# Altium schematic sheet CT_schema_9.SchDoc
size 274 x 160 mm
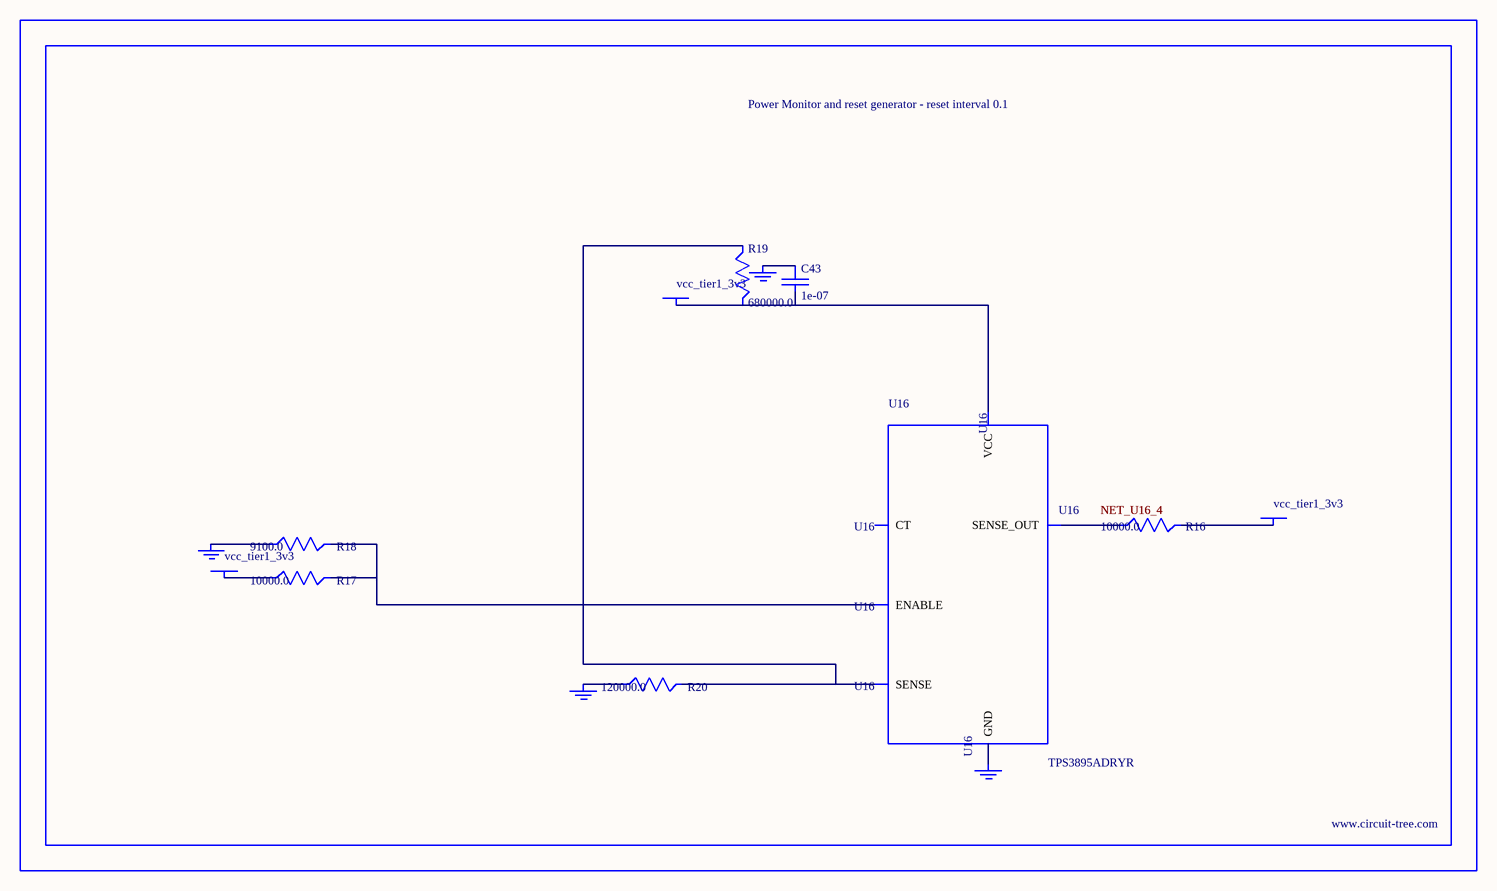
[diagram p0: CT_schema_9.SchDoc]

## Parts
BORDER8  (no value)
C43  1e-07  [C0402]
GND_INSTANCE_8_0  (no value)
GND_INSTANCE_8_1  (no value)
GND_INSTANCE_8_2  (no value)
GND_INSTANCE_8_3  (no value)
POWER_INSTANCE_8_0  vcc_tier1_3v3
POWER_INSTANCE_8_1  vcc_tier1_3v3
POWER_INSTANCE_8_2  vcc_tier1_3v3
R16  10000.0  [R0603]
R17  10000.0  [R0603]
R18  9100.0  [R0603]
R19  680000.0  [R0603]
R20  120000.0  [R0603]
U16  TPS3895ADRYR  [SON-6]

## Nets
NetC43_1: C43.1 GND_INSTANCE_8_2.0(GND)
NetC43_2: C43.2 POWER_INSTANCE_8_2.0(PWR) R19.2 U16.6(VCC)
NetGND_INSTANCE_8_0_0: GND_INSTANCE_8_0.0(GND) R18.1
NetGND_INSTANCE_8_1_0: GND_INSTANCE_8_1.0(GND) R20.1
NetGND_INSTANCE_8_3_0: GND_INSTANCE_8_3.0(GND) U16.2(GND)
NetPOWER_INSTANCE_8_0_0: POWER_INSTANCE_8_0.0(PWR) R17.1
NetPOWER_INSTANCE_8_1_0: POWER_INSTANCE_8_1.0(PWR) R16.2
NetR16_1: R16.1 U16.4(SENSE_OUT)
NetR17_2: R17.2 R18.2 U16.1(ENABLE)
NetR19_1: R19.1 R20.2 U16.3(SENSE)

Not connected (* = marked no-connect by the designer): U16 5(CT)

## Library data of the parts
BORDER8 = BORDER_PAGE8
C43 = C0402C104K3RACTU
GND_INSTANCE_8_0-GND_INSTANCE_8_3 = GND
POWER_INSTANCE_8_0-POWER_INSTANCE_8_2 = PWR
R16 R17 = RC0603JR-0710KL
R18 = RC0603JR-079K1L
R19 = RC0603JR-07680KL
R20 = RC0603JR-07120KL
